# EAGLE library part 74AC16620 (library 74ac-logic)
16-bit BUS TRANSCEIVER, 3-state
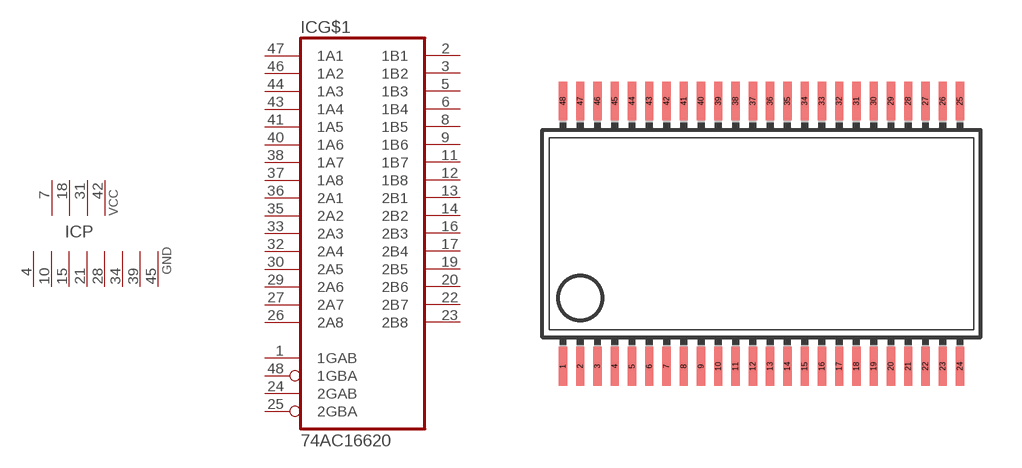
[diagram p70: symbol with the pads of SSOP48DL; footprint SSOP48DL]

Designator prefix IC; gates G$1=7416620 P=4PWR8GND

## 74AC16620  [SSOP48DL]
1  G$1:1GAB  in
2  G$1:1B1
3  G$1:1B2
4  P:GND  pwr
5  G$1:1B3
6  G$1:1B4
7  P:VCC  pwr
8  G$1:1B5
9  G$1:1B6
10  P:GND  pwr
11  G$1:1B7
12  G$1:1B8
13  G$1:2B1
14  G$1:2B2
15  P:GND  pwr
16  G$1:2B3
17  G$1:2B4
18  P:VCC  pwr
19  G$1:2B5
20  G$1:2B6
21  P:GND  pwr
22  G$1:2B7
23  G$1:2B8
24  G$1:2GAB  in
25  G$1:2GBA  in
26  G$1:2A8
27  G$1:2A7
28  P:GND  pwr
29  G$1:2A6
30  G$1:2A5
31  P:VCC  pwr
32  G$1:2A4
33  G$1:2A3
34  P:GND  pwr
35  G$1:2A2
36  G$1:2A1
37  G$1:1A8
38  G$1:1A7
39  P:GND  pwr
40  G$1:1A6
41  G$1:1A5
42  P:VCC  pwr
43  G$1:1A4
44  G$1:1A3
45  P:GND  pwr
46  G$1:1A2
47  G$1:1A1
48  G$1:1GBA  in

## Footprint SSOP48DL (pad centres in mm)
Shrink Small Outline Package
smd 0.305 x 1.422: 1 -6.985,-4.877; 2 -6.35,-4.877; 3 -5.715,-4.877; 4 -5.08,-4.877; 5 -4.445,-4.877; 6 -3.81,-4.877; 7 -3.175,-4.877; 8 -2.54,-4.877; 9 -1.905,-4.877; 10 -1.27,-4.877; 11 -0.635,-4.877; 12 0,-4.877; 13 0.635,-4.877; 14 1.27,-4.877; 15 1.905,-4.877; 16 2.54,-4.877; 17 3.175,-4.877; 18 3.81,-4.877; 19 4.445,-4.877; 20 5.08,-4.877; 21 5.715,-4.877; 22 6.35,-4.877; 23 6.985,-4.877; 24 7.62,-4.877; 25 7.62,4.877; 26 6.985,4.877; 27 6.35,4.877; 28 5.715,4.877; 29 5.08,4.877; 30 4.445,4.877; 31 3.81,4.877; 32 3.175,4.877; 33 2.54,4.877; 34 1.905,4.877; 35 1.27,4.877; 36 0.635,4.877; 37 0,4.877; 38 -0.635,4.877; 39 -1.27,4.877; 40 -1.905,4.877; 41 -2.54,4.877; 42 -3.175,4.877; 43 -3.81,4.877; 44 -4.445,4.877; 45 -5.08,4.877; 46 -5.715,4.877; 47 -6.35,4.877; 48 -6.985,4.877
